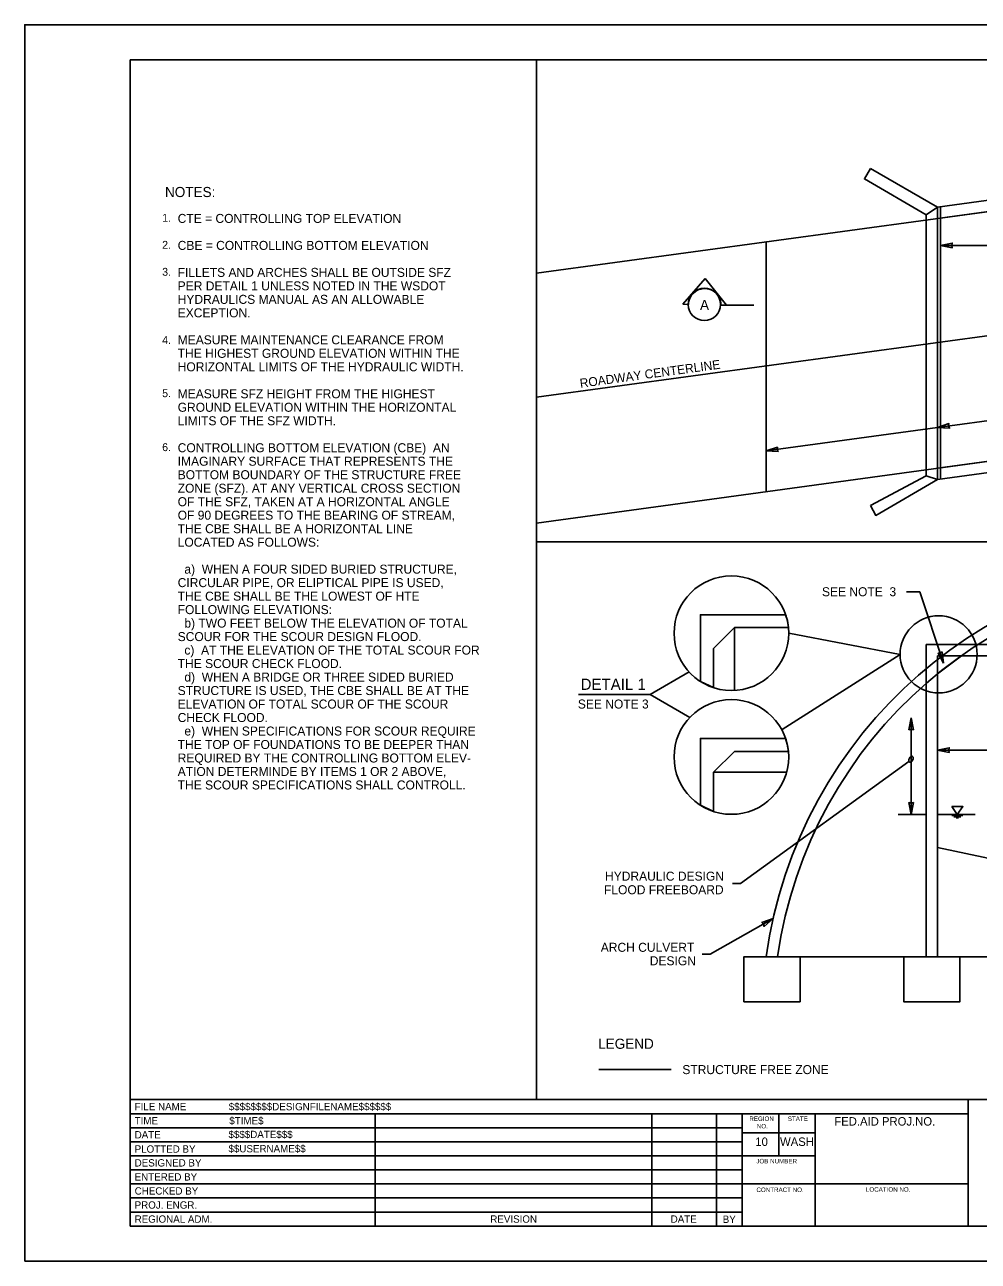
# Model space of a CAD drawing. Extents: x 99988 to 100090, y 99986 to 100024.
# Drawn here: x 100059.12 to 100067.61, y 99999.62 to 100010.62 of the extents above; entities that cross this region are included whole.
import ezdxf

# ---------------------------------------------------------------- set-up
doc = ezdxf.new("R2010")
doc.units = 0
for name, color, linetype in [('Default', 7, 'Continuous'), ('Level 1', 7, 'Continuous'), ('Level 15', 7, 'Continuous'), ('Level 20', 7, 'Continuous'), ('Level 22', 7, 'Continuous'), ('Level 4', 7, 'Continuous'), ('Level 6', 7, 'Continuous'), ('Level 8', 7, 'Continuous'), ('RD_ED_RoadwayETWPaved', 7, 'Continuous'), ('SH_DP_WaterSurfaceElev', 7, 'Continuous'), ('SH_GI_PlotLimits', 7, 'Continuous'), ('SH_GI_SheetBorder', 7, 'Continuous'), ('SH_GI_SheetTextInCells', 7, 'Continuous'), ('SH_GI_TitleBlockText', 7, 'Continuous')]:
    doc.layers.add(name, color=color, linetype=linetype)

msp = doc.modelspace()

# ---------------------------------------------------------------- linework, layer by layer
at = {"layer": 'Default'}
for p, q in [((100063.679, 100001.063), (100063.679, 100010.312)), ((100067.272, 100008.512), (100067.272, 100008.812)), ((100064.234, 100001.33), (100064.877, 100001.33))]:
    msp.add_line(p, q, dxfattribs=at)
at = {"layer": 'Level 1'}
for p, q in [((100065.823, 100002.334), (100065.723, 100002.334)), ((100066.023, 100002.334), (100066.946, 100002.334))]:
    msp.add_line(p, q, dxfattribs=at)
msp.add_lwpolyline([(100065.723, 100006.834), (100065.827, 100006.828), (100065.819, 100006.847), (100065.821, 100006.867)], close=True, dxfattribs=at)
msp.add_lwpolyline([(100065.723, 100006.834), (100065.827, 100006.828), (100065.819, 100006.847), (100065.821, 100006.867)], close=True, dxfattribs=at)
msp.add_lwpolyline([(100065.723, 100002.334), (100065.523, 100002.334), (100065.523, 100001.934), (100065.723, 100001.934), (100066.023, 100001.934), (100066.023, 100002.334), (100065.823, 100002.334)], dxfattribs=at)
at = {"layer": 'Level 15'}
for p, q in [((100063.679, 100007.311), (100075.812, 100008.968)), ((100067.272, 100008.662), (100072.21, 100008.662)), ((100067.246, 100007.042), (100072.246, 100007.725)), ((100065.922, 100005.212), (100066.913, 100005.024)), ((100066.913, 100005.024), (100065.864, 100004.356)), ((100067.011, 100004.459), (100067.011, 100003.6)), ((100067.246, 100004.172), (100070.794, 100004.172)), ((100066.897, 100003.6), (100067.146, 100003.6)), ((100067.246, 100003.6), (100067.582, 100003.6))]:
    msp.add_line(p, q, dxfattribs=at)
for points in [[(100067.272, 100008.662), (100067.377, 100008.641), (100067.372, 100008.662), (100067.377, 100008.682)], [(100067.246, 100007.042), (100067.353, 100007.036), (100067.345, 100007.056), (100067.347, 100007.077)], [(100067.3, 100004.947), (100067.287, 100005.046), (100067.27, 100005.035), (100067.251, 100005.034)], [(100067.011, 100004.459), (100067.032, 100004.354), (100067.011, 100004.359), (100066.991, 100004.354)], [(100067.246, 100004.172), (100067.351, 100004.152), (100067.346, 100004.172), (100067.351, 100004.193)], [(100067.011, 100003.6), (100067.032, 100003.705), (100067.011, 100003.7), (100066.991, 100003.705)], [(100065.784, 100002.673), (100065.683, 100002.64), (100065.697, 100002.624), (100065.703, 100002.604)]]:
    msp.add_lwpolyline(points, close=True, dxfattribs=at)
for points in [[(100067.3, 100004.947), (100067.088, 100005.579), (100066.97, 100005.579)], [(100066.991, 100004.072), (100065.492, 100002.986), (100065.422, 100002.986)], [(100065.784, 100002.673), (100065.222, 100002.357), (100065.152, 100002.357)]]:
    msp.add_lwpolyline(points, dxfattribs=at)
for centre, radius in [((100065.412, 100005.212), 0.51), ((100067.256, 100005.024), 0.343), ((100065.412, 100004.111), 0.51)]:
    msp.add_circle(centre, radius, dxfattribs=at)
msp.add_ellipse((100067.01, 100004.091), major_axis=(0.0144, 0.0249), ratio=0.57735, dxfattribs=at)
at = {"layer": 'Level 20'}
for p, q in [((100065.179, 100008.367), (100064.979, 100008.139)), ((100065.369, 100008.13), (100065.179, 100008.367)), ((100064.979, 100008.139), (100065.03, 100008.137)), ((100065.315, 100008.131), (100065.611, 100008.131)), ((100065.318, 100008.131), (100065.369, 100008.13))]:
    msp.add_line(p, q, dxfattribs=at)
for points in [[(100065.036, 100004.868), (100064.689, 100004.667), (100064.051, 100004.667)], [(100065.043, 100004.463), (100064.689, 100004.667), (100064.619, 100004.667)]]:
    msp.add_lwpolyline(points, dxfattribs=at)
msp.add_circle((100065.172, 100008.137), 0.144, dxfattribs=at)
msp.add_arc((100065.174, 100008.134), 0.144, 358.796, 178.8005, dxfattribs=at)
at = {"layer": 'Level 22'}
for p, q in [((100065.92, 100005.262), (100065.91, 100005.324)), ((100065.137, 100004.783), (100065.252, 100004.728)), ((100065.92, 100004.161), (100065.909, 100004.224)), ((100065.137, 100003.682), (100065.252, 100003.627)), ((100067.246, 100002.334), (100067.146, 100002.334))]:
    msp.add_line(p, q, dxfattribs=at)
for points in [[(100067.246, 100009.002), (100072.246, 100009.686), (100072.246, 100009.585), (100067.246, 100008.902)], [(100066.649, 100009.347), (100067.246, 100009.002), (100067.146, 100008.935), (100067.146, 100008.935), (100066.595, 100009.253)], [(100067.246, 100009.002), (100067.146, 100008.935), (100067.146, 100006.612), (100067.246, 100006.578)], [(100067.246, 100006.679), (100072.246, 100007.362), (100072.246, 100007.261), (100067.246, 100006.578)], [(100066.649, 100006.349), (100067.146, 100006.612), (100067.246, 100006.578), (100067.246, 100006.578), (100066.696, 100006.26)], [(100067.146, 100005.112), (100072.346, 100005.112), (100072.346, 100005.012), (100072.346, 100002.334), (100072.246, 100002.334), (100072.246, 100004.85), (100072.033, 100005.012), (100067.459, 100005.012), (100067.246, 100004.85), (100067.246, 100002.334), (100067.146, 100002.334), (100067.146, 100005.012)]]:
    msp.add_lwpolyline(points, close=True, dxfattribs=at)
for points in [[(100065.91, 100005.324), (100065.895, 100005.377), (100065.137, 100005.377), (100065.137, 100004.783)], [(100065.252, 100004.728), (100065.252, 100005.076), (100065.441, 100005.262), (100065.92, 100005.262)], [(100065.909, 100004.224), (100065.895, 100004.276), (100065.137, 100004.276), (100065.137, 100003.682)], [(100065.252, 100003.627), (100065.252, 100003.975), (100065.441, 100004.161), (100065.92, 100004.161)], [(100067.146, 100002.334), (100066.946, 100002.334), (100066.946, 100001.934), (100067.146, 100001.934), (100067.446, 100001.934), (100067.446, 100002.334), (100067.246, 100002.334)]]:
    msp.add_lwpolyline(points, dxfattribs=at)
at = {"layer": 'Level 4'}
msp.add_line((100067.272, 100006.581), (100067.272, 100009.006), dxfattribs=at)
for points in [[(100065.92, 100005.262), (100065.441, 100005.262), (100065.441, 100004.703)], [(100065.903, 100003.975), (100065.252, 100003.975), (100065.252, 100003.627)]]:
    msp.add_lwpolyline(points, dxfattribs=at)
msp.add_lwpolyline([(100067.246, 100005.012), (100072.246, 100005.012), (100072.246, 100002.334), (100067.246, 100002.334)], close=True, dxfattribs=at)
at = {"layer": 'Level 6'}
msp.add_lwpolyline([(100067.246, 100003.307), (100068.564, 100003.026), (100069.193, 100002.62), (100069.817, 100002.518), (100070.441, 100002.62), (100071.069, 100003.026), (100072.246, 100003.307)], dxfattribs=at)
at = {"layer": 'Level 8'}
for p, q in [((100065.723, 100008.693), (100065.723, 100006.471)), ((100065.723, 100006.834), (100067.246, 100007.042))]:
    msp.add_line(p, q, dxfattribs=at)
for radius, start, end in [(4.062, 7.8759, 172.1241), (3.962, 8.076, 171.924)]:
    msp.add_arc((100069.746, 100001.777), radius, start, end, dxfattribs=at)
at = {"layer": 'RD_ED_RoadwayETWPaved'}
for p, q in [((100063.679, 100008.414), (100075.812, 100010.072)), ((100063.679, 100006.191), (100075.812, 100007.849))]:
    msp.add_line(p, q, dxfattribs=at)
at = {"layer": 'SH_DP_WaterSurfaceElev'}
for p, q in [((100067.372, 100003.59), (100067.472, 100003.59)), ((100067.392, 100003.58), (100067.452, 100003.58)), ((100067.412, 100003.57), (100067.432, 100003.57))]:
    msp.add_line(p, q, dxfattribs=at)
msp.add_lwpolyline([(100067.372, 100003.67), (100067.472, 100003.67), (100067.422, 100003.6)], close=True, dxfattribs=at)
at = {"layer": 'SH_GI_PlotLimits'}
msp.add_lwpolyline([(100059.125, 99999.625), (100076.125, 99999.625), (100076.125, 100010.625), (100059.125, 100010.625)], close=True, dxfattribs=at)
at = {"layer": 'SH_GI_SheetBorder'}
for p, q in [((100060.062, 100010.312), (100060.062, 99999.937)), ((100060.062, 100010.312), (100075.812, 100010.312)), ((100075.812, 100006.026), (100063.679, 100006.026)), ((100060.062, 100001.063), (100075.812, 100001.063)), ((100067.519, 99999.937), (100067.519, 100001.063)), ((100060.062, 100000.938), (100067.519, 100000.938)), ((100062.242, 100000.938), (100062.242, 99999.937)), ((100064.703, 100000.938), (100064.703, 99999.937)), ((100065.279, 100000.938), (100065.279, 99999.937)), ((100065.508, 100000.938), (100065.508, 99999.937)), ((100065.834, 100000.563), (100065.834, 100000.938)), ((100066.158, 99999.937), (100066.158, 100000.938)), ((100060.062, 100000.813), (100062.245, 100000.813)), ((100062.245, 100000.813), (100065.509, 100000.813)), ((100060.062, 100000.688), (100062.245, 100000.688)), ((100062.245, 100000.688), (100065.509, 100000.688)), ((100066.158, 100000.768), (100065.509, 100000.768)), ((100060.062, 100000.563), (100065.509, 100000.563)), ((100066.158, 100000.563), (100065.509, 100000.563)), ((100060.062, 100000.438), (100065.509, 100000.438)), ((100060.062, 100000.313), (100065.509, 100000.313)), ((100067.519, 100000.313), (100065.509, 100000.313)), ((100060.062, 100000.188), (100065.509, 100000.188)), ((100060.062, 100000.063), (100065.509, 100000.063)), ((100060.062, 99999.937), (100075.812, 99999.937))]:
    msp.add_line(p, q, dxfattribs=at)

# ---------------------------------------------------------------- texts
at = {"layer": 'Level 1'}
for s, height, p in [('NOTES: ', 0.09, (100060.373, 100009.092)), ('1.', 0.07, (100060.348, 100008.872)), ('CTE = CONTROLLING TOP ELEVATION', 0.08, (100060.486, 100008.862)), ('2.', 0.07, (100060.348, 100008.632)), ('CBE = CONTROLLING BOTTOM ELEVATION', 0.08, (100060.486, 100008.622)), ('3.', 0.07, (100060.348, 100008.392)), ('FILLETS AND ARCHES SHALL BE OUTSIDE SFZ ', 0.08, (100060.486, 100008.382)), ('PER DETAIL 1 UNLESS NOTED IN THE WSDOT ', 0.08, (100060.486, 100008.262)), ('HYDRAULICS MANUAL AS AN ALLOWABLE ', 0.08, (100060.486, 100008.142)), ('EXCEPTION.', 0.08, (100060.486, 100008.022)), ('4.', 0.07, (100060.348, 100007.785)), ('MEASURE MAINTENANCE CLEARANCE FROM ', 0.08, (100060.486, 100007.782)), ('THE HIGHEST GROUND ELEVATION WITHIN THE ', 0.08, (100060.486, 100007.662)), ('HORIZONTAL LIMITS OF THE HYDRAULIC WIDTH.   ', 0.08, (100060.486, 100007.542)), ('5.', 0.07, (100060.348, 100007.312)), ('MEASURE SFZ HEIGHT FROM THE HIGHEST ', 0.08, (100060.486, 100007.302)), ('GROUND ELEVATION WITHIN THE HORIZONTAL ', 0.08, (100060.486, 100007.182)), ('LIMITS OF THE SFZ WIDTH.', 0.08, (100060.486, 100007.062)), ('6.', 0.07, (100060.348, 100006.832)), ('CONTROLLING BOTTOM ELEVATION (CBE)  AN ', 0.08, (100060.486, 100006.822)), ('IMAGINARY SURFACE THAT REPRESENTS THE ', 0.08, (100060.486, 100006.702)), ('BOTTOM BOUNDARY OF THE STRUCTURE FREE ', 0.08, (100060.486, 100006.582)), ('ZONE (SFZ). AT ANY VERTICAL CROSS SECTION ', 0.08, (100060.486, 100006.462)), ('OF THE SFZ, TAKEN AT A HORIZONTAL ANGLE ', 0.08, (100060.486, 100006.342)), ('OF 90 DEGREES TO THE BEARING OF STREAM, ', 0.08, (100060.486, 100006.222)), ('THE CBE SHALL BE A HORIZONTAL LINE ', 0.08, (100060.486, 100006.102)), ('LOCATED AS FOLLOWS:', 0.08, (100060.486, 100005.982)), ('  a)  WHEN A FOUR SIDED BURIED STRUCTURE, ', 0.08, (100060.486, 100005.742)), ('CIRCULAR PIPE, OR ELIPTICAL PIPE IS USED,', 0.08, (100060.486, 100005.622)), ('THE CBE SHALL BE THE LOWEST OF HTE ', 0.08, (100060.486, 100005.502)), ('FOLLOWING ELEVATIONS:', 0.08, (100060.486, 100005.382)), ('  b) TWO FEET BELOW THE ELEVATION OF TOTAL ', 0.08, (100060.486, 100005.262)), ('SCOUR FOR THE SCOUR DESIGN FLOOD.', 0.08, (100060.486, 100005.142)), ('  c)  AT THE ELEVATION OF THE TOTAL SCOUR FOR ', 0.08, (100060.486, 100005.022)), ('THE SCOUR CHECK FLOOD.', 0.08, (100060.486, 100004.902)), ('  d)  WHEN A BRIDGE OR THREE SIDED BURIED ', 0.08, (100060.486, 100004.782)), ('STRUCTURE IS USED, THE CBE SHALL BE AT THE ', 0.08, (100060.486, 100004.662)), ('ELEVATION OF TOTAL SCOUR OF THE SCOUR ', 0.08, (100060.486, 100004.542)), ('CHECK FLOOD. ', 0.08, (100060.486, 100004.422)), ('  e)  WHEN SPECIFICATIONS FOR SCOUR REQUIRE ', 0.08, (100060.486, 100004.302)), ('THE TOP OF FOUNDATIONS TO BE DEEPER THAN', 0.08, (100060.486, 100004.182)), ('REQUIRED BY THE CONTROLLING BOTTOM ELEV-', 0.08, (100060.486, 100004.062)), ('ATION DETERMINDE BY ITEMS 1 OR 2 ABOVE, ', 0.08, (100060.486, 100003.942)), ('THE SCOUR SPECIFICATIONS SHALL CONTROLL.', 0.08, (100060.486, 100003.822))]:
    msp.add_text(s, height=height, dxfattribs=at).set_placement(p)
at = {"layer": 'Level 15'}
msp.add_text('DETAIL 1', height=0.1, dxfattribs=at).set_placement((100064.071, 100004.708))
at = {"layer": 'Level 20'}
for s, height, rotation, p in [('A', 0.09, 359.9972, (100065.133, 100008.087)), ('ROADWAY CENTERLINE', 0.08, 7.7791, (100064.069, 100007.395))]:
    msp.add_text(s, height=height, rotation=rotation, dxfattribs=at).set_placement(p)
for s, height, p in [('SEE NOTE  3', 0.08, (100066.218, 100005.541)), ('SEE NOTE 3', 0.08, (100064.046, 100004.542)), ('HYDRAULIC DESIGN', 0.08, (100064.288, 100003.011)), ('FLOOD FREEBOARD', 0.08, (100064.279, 100002.89)), ('ARCH CULVERT', 0.08, (100064.25, 100002.378)), ('DESIGN', 0.08, (100064.686, 100002.258)), ('LEGEND', 0.09, (100064.227, 100001.515)), ('STRUCTURE FREE ZONE', 0.08, (100064.976, 100001.29))]:
    msp.add_text(s, height=height, dxfattribs=at).set_placement(p)
at = {"layer": 'SH_GI_SheetTextInCells'}
for s, height, p in [('FILE NAME', 0.0651, (100060.103, 100000.968)), ('TIME', 0.0651, (100060.103, 100000.843)), ('REGION', 0.04, (100065.572, 100000.873)), ('STATE', 0.04, (100065.914, 100000.873)), ('FED.AID PROJ.NO.', 0.07506, (100066.328, 100000.832)), ('DATE', 0.0651, (100060.103, 100000.718)), ('NO.', 0.04, (100065.638, 100000.807)), ('10', 0.0751, (100065.625, 100000.651)), ('WASH', 0.0751, (100065.845, 100000.651)), ('PLOTTED BY', 0.0651, (100060.103, 100000.591)), ('DESIGNED BY', 0.06505, (100060.103, 100000.468)), ('JOB NUMBER', 0.04, (100065.634, 100000.496)), ('ENTERED BY', 0.0651, (100060.103, 100000.343)), ('CHECKED BY', 0.0651, (100060.103, 100000.218)), ('CONTRACT NO.', 0.04003, (100065.635, 100000.241)), ('LOCATION NO.', 0.04003, (100066.609, 100000.244)), ('PROJ. ENGR.', 0.06505, (100060.103, 100000.093)), ('REGIONAL ADM.', 0.06505, (100060.103, 99999.968)), ('REVISION', 0.0651, (100063.267, 99999.968)), ('DATE', 0.0651, (100064.872, 99999.968)), ('BY', 0.0651, (100065.335, 99999.966))]:
    msp.add_text(s, height=height, dxfattribs=at).set_placement(p)
at = {"layer": 'SH_GI_TitleBlockText'}
for s, height, p in [('$$$$$$$$DESIGNFILENAME$$$$$$', 0.06505, (100060.94, 100000.968)), ('$TIME$', 0.0651, (100060.945, 100000.843)), ('$$$$DATE$$$', 0.06505, (100060.938, 100000.721)), ('$$USERNAME$$', 0.06505, (100060.938, 100000.594))]:
    msp.add_text(s, height=height, dxfattribs=at).set_placement(p)

doc.saveas('drawing.dxf')
